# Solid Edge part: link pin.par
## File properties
Author: Robert a Rhodes jr
Template: Normal.par
Last saved by: CADCIM
Revision: 9
Application: Solid Edge
Accuracy: 0.99
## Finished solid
Body 1: solid body, 5 faces, 4 edges, 0 vertices.
  Faces by surface: plane 3, cylinder 2
  Edges by curve: circle 4
Bounding box of the edges (mm): 15.000 x 15.000 x 50.000, from (-7.5, -7.5, -22.7536) to (7.5, 7.5, 27.2464).
Cylindrical faces by radius (mm): R5 x1, R7.5 x1
Planar faces by outward normal: +z 1, -z 2
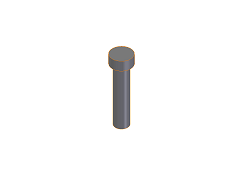
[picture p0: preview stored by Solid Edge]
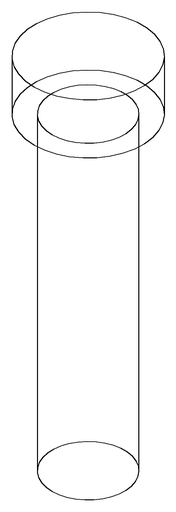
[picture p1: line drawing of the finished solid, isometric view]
